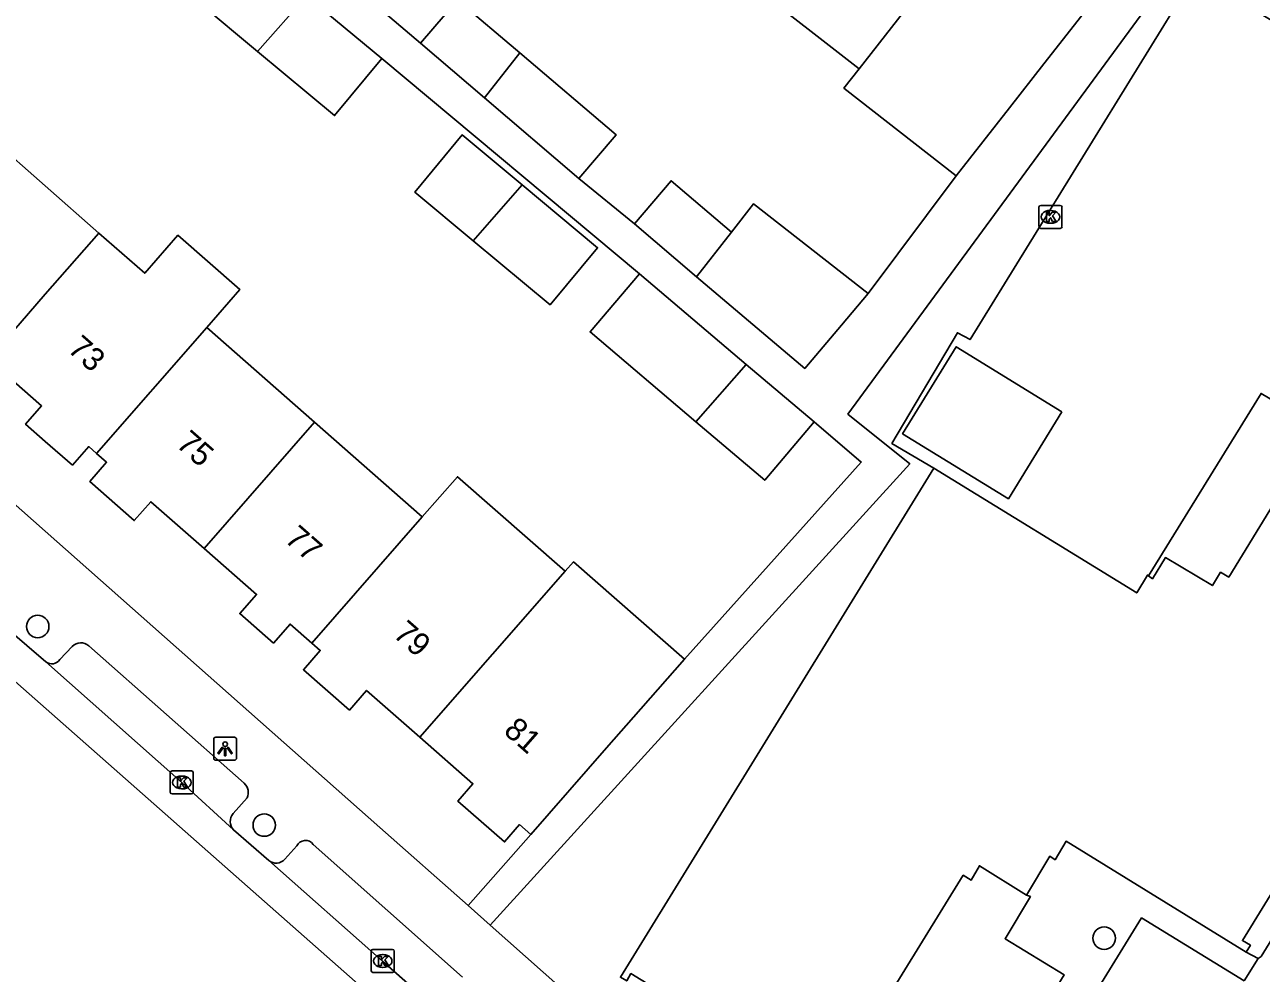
# Model space of a CAD drawing. Extents: x 162812 to 163818, y 381639 to 382470.
# Drawn here: x 162999.1 to 163052.9, y 381861.1 to 381902.4 of the extents above; entities that cross this region are included whole.
import ezdxf

# ---------------------------------------------------------------- set-up
doc = ezdxf.new("R2010")
doc.units = 0
for name, color, linetype in [('IMGEO_Boom', 7, 'Continuous'), ('IMGEO_Hek', 7, 'Continuous'), ('IMGEO_Kolk', 7, 'Continuous'), ('IMGEO_Lichtpunt', 7, 'Continuous'), ('IMGEO_Open_loods', 7, 'Continuous'), ('IMGEO_Pand', 7, 'Continuous'), ('IMGEO_Pand_nummerreeks', 7, 'Continuous'), ('IMGEO_Parkeervlak_open', 7, 'Continuous'), ('IMGEO_Rijbaan_lokaal_gesloten', 7, 'Continuous'), ('IMGEO_Voetpad_gesloten', 7, 'Continuous'), ('IMGEO_Voetpad_halfverhard', 7, 'Continuous'), ('IMGEO_Voetpad_open', 7, 'Continuous')]:
    doc.layers.add(name, color=color, linetype=linetype)

msp = doc.modelspace()

# ---------------------------------------------------------------- linework, layer by layer
at = {"layer": 'IMGEO_Boom'}
for centre in [(162999.67, 381876.203), (163009.526, 381867.569), (163046.064, 381862.651)]:
    msp.add_circle(centre, 0.489, dxfattribs=at)
at = {"layer": 'IMGEO_Hek'}
msp.add_lwpolyline([(163050.243, 381906.292), (163034.914, 381885.439), (163037.605, 381883.275), (163019.349, 381863.218)], dxfattribs=at)
at = {"layer": 'IMGEO_Kolk'}
for p, q in [((163043.226, 381893.583), (163043.226, 381894.435)), ((163043.301, 381894.509), (163044.153, 381894.509)), ((163043.714, 381894.289), (163043.739, 381894.289)), ((163044.227, 381894.435), (163044.227, 381893.583)), ((163043.737, 381893.729), (163043.712, 381893.729)), ((163044.153, 381893.509), (163043.301, 381893.509)), ((163005.437, 381868.996), (163005.437, 381869.848)), ((163005.512, 381869.922), (163006.364, 381869.922)), ((163005.925, 381869.702), (163005.95, 381869.702)), ((163006.438, 381869.848), (163006.438, 381868.996)), ((163006.364, 381868.922), (163005.512, 381868.922)), ((163005.948, 381869.142), (163005.923, 381869.142)), ((163014.179, 381861.234), (163014.179, 381862.086)), ((163014.254, 381862.16), (163015.106, 381862.16)), ((163014.667, 381861.94), (163014.692, 381861.94)), ((163015.18, 381862.086), (163015.18, 381861.234)), ((163014.69, 381861.38), (163014.665, 381861.38)), ((163015.106, 381861.16), (163014.254, 381861.16))]:
    msp.add_line(p, q, dxfattribs=at)
for points in [[(163043.226, 381893.583), (163043.226, 381894.435)], [(163043.301, 381894.509), (163044.153, 381894.509)], [(163043.547, 381894.209), (163043.67, 381894.209), (163043.67, 381894.058), (163043.8, 381894.209), (163043.964, 381894.209), (163043.818, 381894.058), (163043.971, 381893.809), (163043.819, 381893.809), (163043.734, 381893.973), (163043.67, 381893.906), (163043.67, 381893.809), (163043.547, 381893.809), (163043.547, 381894.209)], [(163044.227, 381894.435), (163044.227, 381893.583)], [(163044.153, 381893.509), (163043.301, 381893.509)], [(163005.437, 381868.996), (163005.437, 381869.848)], [(163005.512, 381869.922), (163006.364, 381869.922)], [(163005.758, 381869.622), (163005.881, 381869.622), (163005.881, 381869.471), (163006.011, 381869.622), (163006.175, 381869.622), (163006.029, 381869.471), (163006.182, 381869.222), (163006.03, 381869.222), (163005.945, 381869.386), (163005.881, 381869.319), (163005.881, 381869.222), (163005.758, 381869.222), (163005.758, 381869.622)], [(163006.438, 381869.848), (163006.438, 381868.996)], [(163006.364, 381868.922), (163005.512, 381868.922)], [(163014.179, 381861.234), (163014.179, 381862.086)], [(163014.254, 381862.16), (163015.106, 381862.16)], [(163015.18, 381862.086), (163015.18, 381861.234)], [(163014.5, 381861.86), (163014.623, 381861.86), (163014.623, 381861.709), (163014.753, 381861.86), (163014.917, 381861.86), (163014.771, 381861.709), (163014.924, 381861.46), (163014.772, 381861.46), (163014.687, 381861.624), (163014.623, 381861.557), (163014.623, 381861.46), (163014.5, 381861.46), (163014.5, 381861.86)], [(163015.106, 381861.16), (163014.254, 381861.16)]]:
    msp.add_lwpolyline(points, dxfattribs=at)
for centre, start, end in [((163043.303, 381894.433), 91.552, 178.448), ((163043.303, 381894.433), 91.552, 178.448), ((163044.151, 381894.433), 1.552, 88.448), ((163044.151, 381894.433), 1.552, 88.448), ((163043.303, 381893.585), 181.552, 268.448), ((163043.303, 381893.585), 181.552, 268.448), ((163044.151, 381893.585), 271.552, 358.448), ((163044.151, 381893.585), 271.552, 358.448), ((163005.514, 381869.846), 91.552, 178.448), ((163005.514, 381869.846), 91.552, 178.448), ((163006.362, 381869.846), 1.552, 88.448), ((163006.362, 381869.846), 1.552, 88.448), ((163005.514, 381868.998), 181.552, 268.448), ((163005.514, 381868.998), 181.552, 268.448), ((163006.362, 381868.998), 271.552, 358.448), ((163006.362, 381868.998), 271.552, 358.448), ((163014.256, 381862.084), 91.552, 178.448), ((163014.256, 381862.084), 91.552, 178.448), ((163015.104, 381862.084), 1.552, 88.448), ((163015.104, 381862.084), 1.552, 88.448), ((163014.256, 381861.236), 181.552, 268.448), ((163014.256, 381861.236), 181.552, 268.448), ((163015.104, 381861.236), 271.552, 358.448), ((163015.104, 381861.236), 271.552, 358.448)]:
    msp.add_arc(centre, 0.0765, start, end, dxfattribs=at)
for centre, major_axis, ratio, start_param, end_param in [((163043.713, 381894.009), (-0.387, 0.002), 0.722429, 4.712389, 7.853982), ((163043.738, 381894.009), (-0.39, 0.002), 0.717154, 1.570796, 4.712389), ((163005.924, 381869.422), (-0.387, 0.002), 0.722429, 4.712389, 7.853982), ((163005.949, 381869.422), (-0.39, 0.002), 0.717154, 1.570796, 4.712389), ((163014.666, 381861.66), (-0.387, 0.002), 0.722429, 4.712389, 7.853982), ((163014.691, 381861.66), (-0.39, 0.002), 0.717154, 1.570796, 4.712389)]:
    msp.add_ellipse(centre, major_axis=major_axis, ratio=ratio, start_param=start_param, end_param=end_param, dxfattribs=at)
at = {"layer": 'IMGEO_Lichtpunt'}
for p, q in [((163007.325, 381871.289), (163007.325, 381870.482)), ((163007.325, 381871.289), (163007.325, 381870.482)), ((163008.227, 381871.384), (163007.419, 381871.384)), ((163008.227, 381871.384), (163007.419, 381871.384)), ((163008.321, 381870.482), (163008.321, 381871.289)), ((163008.321, 381870.482), (163008.321, 381871.289)), ((163007.419, 381870.388), (163008.227, 381870.388)), ((163007.419, 381870.388), (163008.227, 381870.388))]:
    msp.add_line(p, q, dxfattribs=at)
for points in [[(163007.699, 381870.953), (163007.738, 381870.925), (163007.55, 381870.663), (163007.512, 381870.69), (163007.699, 381870.953)], [(163007.801, 381870.905), (163007.848, 381870.905), (163007.848, 381870.583), (163007.801, 381870.583), (163007.801, 381870.905)], [(163007.911, 381870.925), (163007.949, 381870.952), (163008.136, 381870.69), (163008.097, 381870.662), (163007.911, 381870.925)]]:
    msp.add_lwpolyline(points, dxfattribs=at)
msp.add_circle((163007.824, 381871.087), 0.0994, dxfattribs=at)
for centre, start, end in [((163007.419, 381871.289), 90, 180), ((163007.419, 381871.289), 90, 180), ((163008.227, 381871.289), 0, 90), ((163008.227, 381871.289), 0, 90), ((163007.419, 381870.482), 180, 270), ((163007.419, 381870.482), 180, 270), ((163008.227, 381870.482), 270, 0), ((163008.227, 381870.482), 270, 360)]:
    msp.add_arc(centre, 0.0946, start, end, dxfattribs=at)
at = {"layer": 'IMGEO_Open_loods'}
msp.add_lwpolyline([(163044.218, 381885.539), (163039.624, 381888.364), (163037.291, 381884.581), (163041.895, 381881.752), (163044.218, 381885.539)], dxfattribs=at)
at = {"layer": 'IMGEO_Pand'}
for points in [[(163035.402, 381900.447), (163037.065, 381902.574), (163041.636, 381908.421)], [(163009.236, 381901.193), (163006.689, 381903.311), (163008.754, 381905.794)], [(163039.628, 381895.786), (163041.95, 381898.756), (163043.442, 381900.664), (163046.521, 381904.603)], [(163030.653, 381904.16), (163035.402, 381900.447)], [(163011.364, 381903.623), (163009.236, 381901.193)], [(163014.646, 381900.893), (163011.364, 381903.623)], [(163016.322, 381901.554), (163017.936, 381903.448), (163020.641, 381901.143)], [(163014.646, 381900.893), (163012.581, 381898.41), (163009.236, 381901.193)], [(163016.322, 381901.554), (163019.108, 381899.18)], [(163019.108, 381899.18), (163020.641, 381901.143)], [(163020.641, 381901.143), (163024.827, 381897.576), (163023.213, 381895.682)], [(163035.402, 381900.447), (163034.743, 381899.605), (163039.628, 381895.786)], [(163019.108, 381899.18), (163023.213, 381895.682)], [(163018.615, 381892.969), (163016.068, 381895.087), (163018.133, 381897.57), (163020.742, 381895.399)], [(162997.647, 381897.414), (163000, 381895.351), (163002.332, 381893.306)], [(163020.742, 381895.399), (163024.025, 381892.669), (163021.96, 381890.186), (163018.615, 381892.969)], [(163020.742, 381895.399), (163018.615, 381892.969)], [(163025.63, 381893.703), (163027.222, 381895.579), (163029.852, 381893.348)], [(163035.802, 381890.676), (163030.812, 381894.576), (163029.852, 381893.348)], [(163025.63, 381893.703), (163028.335, 381891.407)], [(162997.523, 381887.813), (163000, 381890.642), (163002.332, 381893.306)], [(163002.332, 381893.306), (163004.326, 381891.558), (163005.771, 381893.209), (163008.469, 381890.848), (163007.021, 381889.194)], [(163029.852, 381893.348), (163028.335, 381891.407)], [(163052.243, 381862.047), (163052.426, 381862.343), (163052.073, 381862.544), (163067.621, 381887.819), (163067.971, 381887.615), (163068.12, 381887.891), (163060.306, 381892.706), (163055.376, 381884.686)], [(163028.306, 381885.099), (163023.698, 381889.004), (163025.843, 381891.535)], [(163030.492, 381887.595), (163025.843, 381891.535)], [(163028.335, 381891.407), (163033.037, 381887.418), (163034.629, 381889.294), (163035.802, 381890.676)], [(163007.021, 381889.194), (163002.233, 381883.724)], [(163007.021, 381889.194), (163011.711, 381885.082)], [(162997.523, 381887.813), (162999.837, 381885.789), (162999.142, 381884.995), (163000, 381884.245), (163001.178, 381883.215), (163001.888, 381884.026), (163002.233, 381883.724)], [(163030.492, 381887.595), (163028.306, 381885.099)], [(163033.443, 381885.093), (163030.492, 381887.595)], [(163006.907, 381879.594), (163011.711, 381885.082)], [(163011.711, 381885.082), (163016.4, 381880.969)], [(163033.443, 381885.093), (163031.298, 381882.562), (163028.306, 381885.099)], [(163055.376, 381884.686), (163051.48, 381878.348), (163051.127, 381878.561), (163050.773, 381877.977), (163048.727, 381879.199), (163048.162, 381878.277), (163047.993, 381878.397)], [(163002.233, 381883.724), (163002.666, 381883.345), (163001.931, 381882.506), (163003.871, 381880.807), (163004.587, 381881.625), (163006.907, 381879.594)], [(163033.858, 381855.537), (163033.587, 381855.698), (163033.798, 381856.014), (163025.478, 381861.115), (163025.295, 381860.793), (163025.018, 381860.951), (163038.651, 381883.086)], [(163047.993, 381878.397), (163047.942, 381878.433), (163047.476, 381877.66), (163038.651, 381883.086)], [(163016.4, 381880.969), (163017.926, 381882.712), (163022.62, 381878.602)], [(163016.4, 381880.969), (163011.592, 381875.478)], [(163006.907, 381879.594), (163009.19, 381877.595), (163008.459, 381876.76), (163009.925, 381875.477), (163010.648, 381876.304), (163011.592, 381875.478)], [(163016.298, 381871.384), (163022.62, 381878.602)], [(163022.62, 381878.602), (163022.978, 381879.01), (163027.8, 381874.781)], [(163011.592, 381875.478), (163011.958, 381875.158), (163011.225, 381874.321), (163013.227, 381872.568), (163013.973, 381873.42), (163016.298, 381871.384)], [(163021.124, 381867.159), (163024.418, 381870.921), (163025.912, 381872.628), (163027.8, 381874.781)], [(163016.298, 381871.384), (163018.603, 381869.366), (163017.945, 381868.613), (163019.976, 381866.835), (163020.635, 381867.587), (163021.124, 381867.159)], [(163042.683, 381864.525), (163043.696, 381866.214), (163043.929, 381866.063), (163044.407, 381866.863), (163052.243, 381862.047)], [(163033.858, 381855.537), (163039.929, 381865.387), (163040.27, 381865.173), (163040.637, 381865.799), (163042.683, 381864.525)]]:
    msp.add_lwpolyline(points, dxfattribs=at)
at = {"layer": 'IMGEO_Parkeervlak_open'}
msp.add_lwpolyline([(163038.651, 381883.086), (163036.828, 381884.162), (163039.676, 381888.972), (163040.229, 381888.673), (163050.041, 381904.572), (163054.928, 381901.596)], dxfattribs=at)
at = {"layer": 'IMGEO_Rijbaan_lokaal_gesloten'}
for points in [[(163033.586, 381843.037), (162961.909, 381906.251)], [(162998.365, 381876.08), (163000.024, 381874.661)], [(163000.024, 381874.661), (163005.934, 381869.421), (163008.194, 381867.36)], [(163008.194, 381867.36), (163009.728, 381866.027)], [(163009.728, 381866.027), (163014.675, 381861.658), (163017.731, 381858.952)]]:
    msp.add_lwpolyline(points, dxfattribs=at)
at = {"layer": 'IMGEO_Voetpad_gesloten'}
for points in [[(163054.736, 381885.241), (163052.886, 381886.336), (163047.993, 381878.397)], [(163042.683, 381864.525), (163042.857, 381864.459), (163041.755, 381862.626), (163044.321, 381861.059), (163042.746, 381858.478)]]:
    msp.add_lwpolyline(points, dxfattribs=at)
at = {"layer": 'IMGEO_Voetpad_halfverhard'}
for points in [[(163050.243, 381906.292), (163034.914, 381885.439), (163037.605, 381883.275), (163019.349, 381863.218)], [(163013.843, 381903.678), (163016.322, 381901.554)], [(163025.843, 381891.535), (163014.646, 381900.893)], [(163023.213, 381895.682), (163025.63, 381893.703)], [(163035.802, 381890.676), (163039.628, 381895.786)], [(163027.8, 381874.781), (163035.497, 381883.351), (163033.443, 381885.093)], [(163018.388, 381864.069), (163021.124, 381867.159)]]:
    msp.add_lwpolyline(points, dxfattribs=at)
at = {"layer": 'IMGEO_Voetpad_open'}
for points in [[(163018.388, 381864.069), (163014.552, 381867.466), (163000, 381880.34), (162981.702, 381896.529), (162934.017, 381938.656)], [(163068.653, 381891.896), (163069.028, 381888.05), (163068.715, 381887.535), (163052.897, 381861.856), (163052.762, 381861.77)], [(163000.634, 381874.763), (163001.173, 381875.336)], [(163001.891, 381875.355), (163008.651, 381869.389)], [(163008.778, 381868.753), (163008.171, 381868.071)], [(163010.418, 381866.087), (163010.943, 381866.661)], [(163011.653, 381866.729), (163018.155, 381860.959)], [(163019.349, 381863.218), (163018.388, 381864.069)], [(163044.092, 381857.691), (163047.687, 381863.531), (163052.152, 381860.804)], [(163031.785, 381852.208), (163019.349, 381863.218)], [(163052.762, 381861.77), (163052.243, 381862.047)], [(163052.762, 381861.77), (163052.152, 381860.804)]]:
    msp.add_lwpolyline(points, dxfattribs=at)
for centre, radius, start, end in [((163001.542, 381874.986), 0.508, 46.5705, 136.4611), ((163000.279, 381875.012), 0.433, 233.9808, 325.0048), ((163008.283, 381868.985), 0.547, 334.9016, 47.6836), ((163008.573, 381867.728), 0.529, 139.5615, 224.1441), ((163011.318, 381866.484), 0.415, 36.1978, 154.7438), ((163010.042, 381866.412), 0.497, 230.7997, 319.1398)]:
    msp.add_arc(centre, radius, start, end, dxfattribs=at)

# ---------------------------------------------------------------- texts
at = {"layer": 'IMGEO_Pand_nummerreeks'}
for s, rotation, p in [('73', 318.7965, (163000.926, 381888.192)), ('75', 318.7965, (163005.645, 381884.06)), ('77', 318.7965, (163010.364, 381879.929)), ('79', 318.7965, (163015.084, 381875.797)), ('81', 318.7986, (163019.889, 381871.592))]:
    msp.add_text(s, height=1, rotation=rotation, dxfattribs=at).set_placement(p)

doc.saveas('drawing.dxf')
